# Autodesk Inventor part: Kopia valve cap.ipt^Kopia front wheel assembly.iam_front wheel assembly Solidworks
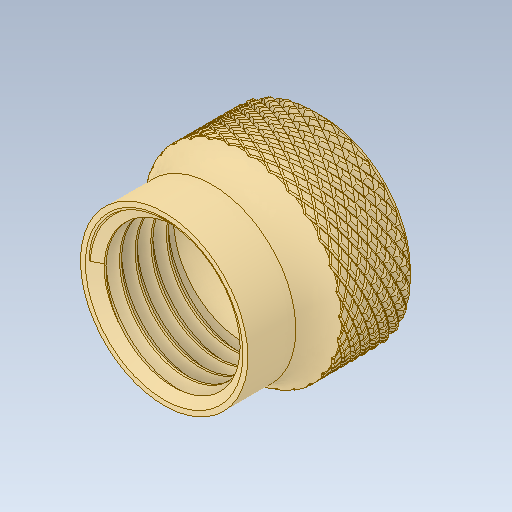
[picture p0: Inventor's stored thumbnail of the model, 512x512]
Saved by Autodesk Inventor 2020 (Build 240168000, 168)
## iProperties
Created: 2017-09
Part Number: Kopia valve cap.ipt^Kopia front wheel assembly.iam_front wheel assembly Solidworks
Material: Ogólny
Document SubType Name: Modeling
Designer: Tomasz
Density: 1 g/cm^3
Appearance: Domyślna
Sending System: SolidWorks 2017
Last Author: Tomasz
Last Saved: 2017-09-11
Author: Tomasz
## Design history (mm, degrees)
feature "valve cap.ipt"
node "Bryła1"
